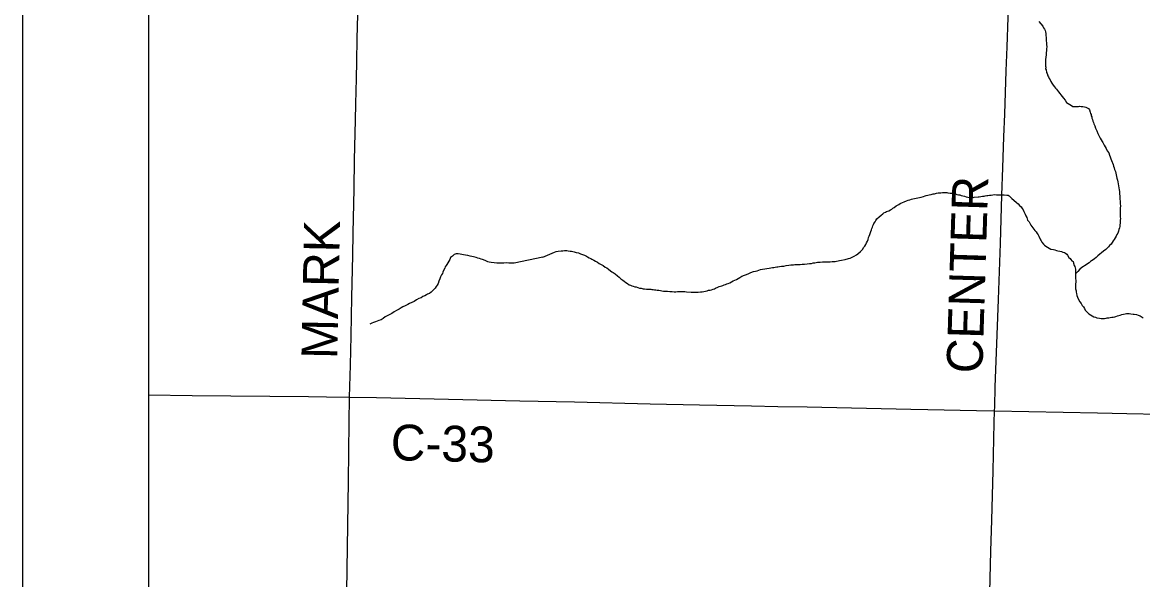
# Model space of a CAD drawing. Extents: x 2.1 to 73.9, y 4 to 26.
# Drawn here: x 41.859 to 42.746, y 22.261 to 22.702 of the extents above; entities that cross this region are included whole.
import ezdxf

# ---------------------------------------------------------------- set-up
doc = ezdxf.new("R2010")
doc.units = 0
for name, color, linetype in [('GM_X_County_Road', 7, 'Continuous'), ('GM_X_County_Road_Text', 7, 'Continuous'), ('GM_X_Minor_River', 7, 'Continuous'), ('GM_X_Township_Road', 7, 'Continuous'), ('GM_X_Township_Road_Text', 7, 'Continuous'), ('SH_Data', 7, 'Continuous')]:
    doc.layers.add(name, color=color, linetype=linetype)

msp = doc.modelspace()

# ---------------------------------------------------------------- linework, layer by layer
at = {"layer": 'GM_X_County_Road'}
for points in [[(42.11768, 22.40528), (42.11831, 22.43051), (42.11882, 22.45382), (42.11946, 22.48459), (42.12015, 22.51753), (42.12049, 22.53524), (42.12117, 22.57036), (42.12166, 22.59335), (42.12239, 22.62474), (42.12266, 22.63779), (42.12313, 22.65767), (42.12339, 22.67135), (42.12371, 22.68907), (42.12411, 22.70833), (42.12441, 22.72822), (42.12463, 22.73723), (42.12492, 22.74998), (42.12514, 22.76365), (42.12565, 22.78757), (42.12612, 22.80528), (42.12662, 22.82827), (42.1272, 22.85469), (42.12765, 22.87831), (42.12836, 22.90514)], [(41.95853, 22.40709), (41.99302, 22.40672), (42.08503, 22.40572), (42.09933, 22.40557), (42.11768, 22.40528)], [(42.11267, 21.90506), (42.11274, 21.91552), (42.11287, 21.92921), (42.11306, 21.99168), (42.11314, 22.01188), (42.11339, 22.03675), (42.11342, 22.04701), (42.11352, 22.06939), (42.11355, 22.08244), (42.11375, 22.10636), (42.11409, 22.1449), (42.11475, 22.19121), (42.11514, 22.22634), (42.1155, 22.2512), (42.11674, 22.33884), (42.11734, 22.38514), (42.11768, 22.40528)], [(42.11768, 22.40528), (42.13911, 22.40494), (42.19598, 22.40361), (42.25255, 22.40241), (42.29574, 22.40145), (42.35573, 22.40007), (42.39489, 22.39932), (42.43591, 22.39845), (42.45674, 22.39798), (42.48005, 22.39755), (42.56209, 22.39575), (42.57577, 22.39544), (42.61431, 22.39477), (42.62854, 22.39452)], [(42.62854, 22.39452), (42.71003, 22.39274), (42.73334, 22.39224), (42.75945, 22.39171), (42.78835, 22.39125), (42.81415, 22.3908), (42.87568, 22.38954), (42.90055, 22.38899), (42.93443, 22.38826), (42.96519, 22.38759), (42.99814, 22.38692), (43.02704, 22.3862), (43.08701, 22.38489), (43.12151, 22.38421), (43.12923, 22.38405)]]:
    msp.add_lwpolyline(points, dxfattribs=at)
at = {"layer": 'GM_X_Minor_River'}
for points in [[(42.66365, 22.70298), (42.66664, 22.69932), (42.66738, 22.69798), (42.66812, 22.69683), (42.66848, 22.69568), (42.66885, 22.69473), (42.66902, 22.69339), (42.66918, 22.69149), (42.66935, 22.69054), (42.66934, 22.6894), (42.66931, 22.68769), (42.66966, 22.68597), (42.66964, 22.68445), (42.66981, 22.68312), (42.66958, 22.68103), (42.66956, 22.6797), (42.66935, 22.67838), (42.66932, 22.67648), (42.6691, 22.67458), (42.66889, 22.67287), (42.66886, 22.67135), (42.66884, 22.66983), (42.66882, 22.6687), (42.6688, 22.66755), (42.66898, 22.6666), (42.66896, 22.66546), (42.66933, 22.66451), (42.66968, 22.6626), (42.67004, 22.66164), (42.67078, 22.65992), (42.67133, 22.65896), (42.67188, 22.65782), (42.67244, 22.65667), (42.67318, 22.65532), (42.67392, 22.65417), (42.67503, 22.65245), (42.67596, 22.6511), (42.67671, 22.65014), (42.67764, 22.64917), (42.67839, 22.64821), (42.67914, 22.64725), (42.68007, 22.64591), (42.681, 22.64475), (42.68212, 22.6434), (42.68305, 22.64206), (42.68435, 22.64052), (42.68547, 22.63879), (42.68942, 22.63626), (42.69037, 22.63567), (42.69132, 22.63566), (42.69283, 22.63544), (42.69398, 22.63561), (42.69493, 22.6356), (42.69588, 22.63577), (42.69721, 22.63556), (42.69835, 22.63554), (42.69968, 22.63533), (42.70081, 22.63494), (42.70176, 22.63454), (42.70289, 22.63395), (42.70382, 22.6328)], [(42.70382, 22.6328), (42.70418, 22.63108), (42.70454, 22.63013), (42.70491, 22.62917), (42.70508, 22.62822), (42.70545, 22.62726), (42.70562, 22.62631), (42.70599, 22.62535), (42.70635, 22.62402), (42.7069, 22.62287), (42.70726, 22.62172), (42.70781, 22.6202), (42.70854, 22.61847), (42.70946, 22.61618), (42.71038, 22.61407), (42.7113, 22.61216), (42.71203, 22.61044), (42.71296, 22.60909), (42.7137, 22.60794), (42.71426, 22.60698), (42.71482, 22.60602), (42.71537, 22.60487), (42.71611, 22.60372), (42.71685, 22.60238), (42.71777, 22.60047), (42.71889, 22.59874), (42.71943, 22.59702), (42.72017, 22.59568), (42.72072, 22.59415), (42.72107, 22.59281), (42.72235, 22.58956), (42.72272, 22.58842), (42.72327, 22.58708), (42.72362, 22.58555), (42.72417, 22.58402), (42.72453, 22.58269), (42.72489, 22.58135), (42.72506, 22.58021), (42.72542, 22.57868), (42.72577, 22.57716), (42.72613, 22.57582), (42.72649, 22.5743), (42.72666, 22.57277), (42.72701, 22.57125), (42.72718, 22.56954), (42.72735, 22.5682), (42.72751, 22.5663), (42.72767, 22.56459), (42.72783, 22.5625), (42.72798, 22.5604), (42.72795, 22.5585), (42.72812, 22.55679), (42.72809, 22.55508), (42.72807, 22.55356), (42.72804, 22.55204), (42.72802, 22.55071), (42.728, 22.54919), (42.72798, 22.54786), (42.72815, 22.54672), (42.72794, 22.54558), (42.72792, 22.54425), (42.7279, 22.54311), (42.72769, 22.54179), (42.72767, 22.54046), (42.72746, 22.53932), (42.72706, 22.538), (42.72666, 22.53667), (42.72607, 22.53516), (42.72529, 22.53422), (42.7247, 22.5329), (42.72392, 22.5314), (42.72333, 22.53027), (42.72255, 22.52914), (42.72177, 22.52782), (42.7208, 22.52651), (42.71964, 22.52538), (42.71867, 22.52445), (42.7179, 22.52351), (42.71674, 22.52239), (42.71481, 22.5209), (42.71038, 22.51717), (42.70903, 22.51605), (42.70768, 22.51493), (42.70653, 22.514), (42.70537, 22.51326), (42.70441, 22.5127), (42.70345, 22.51177), (42.70211, 22.51103), (42.70114, 22.5101), (42.6998, 22.50936), (42.69884, 22.5088), (42.69769, 22.50806), (42.69595, 22.50657), (42.6944, 22.50488), (42.69324, 22.50357), (42.69285, 22.5032), (42.69286, 22.50339)], [(42.54799, 22.55508), (42.54895, 22.55564), (42.55067, 22.55675), (42.55163, 22.55731), (42.5526, 22.55805), (42.55375, 22.5586), (42.55873, 22.5608), (42.56007, 22.56135), (42.5614, 22.56171), (42.56274, 22.56207), (42.56389, 22.56243), (42.56503, 22.56279), (42.56637, 22.56296), (42.5677, 22.56313), (42.56904, 22.56349), (42.57037, 22.56385), (42.57228, 22.56439), (42.57343, 22.56475), (42.57439, 22.56493), (42.57572, 22.56528), (42.57668, 22.56546), (42.5782, 22.56582), (42.57992, 22.56636), (42.58087, 22.56634), (42.58259, 22.56689), (42.58374, 22.56706), (42.58583, 22.56721), (42.58717, 22.56738), (42.58831, 22.56737), (42.58964, 22.56734), (42.59059, 22.56733), (42.59154, 22.56712), (42.59324, 22.56691), (42.59496, 22.56688), (42.5959, 22.56668), (42.59761, 22.56627), (42.59874, 22.56587), (42.59988, 22.56566), (42.60102, 22.56545), (42.60215, 22.56506), (42.60329, 22.56485), (42.60462, 22.56445), (42.60594, 22.56405), (42.60727, 22.56364), (42.60878, 22.56343), (42.6105, 22.56359), (42.61145, 22.56358), (42.6124, 22.56375), (42.61545, 22.56389), (42.6164, 22.56407), (42.61774, 22.56424), (42.61888, 22.56441), (42.62021, 22.56458), (42.62117, 22.56476), (42.62231, 22.56493), (42.62326, 22.5651), (42.62441, 22.56527), (42.62574, 22.56544), (42.62708, 22.56561), (42.62841, 22.56578), (42.62993, 22.56557), (42.63202, 22.56553), (42.63393, 22.56569), (42.63602, 22.56566), (42.6383, 22.56543), (42.63925, 22.56542), (42.64019, 22.56483), (42.64093, 22.56387), (42.64225, 22.56271), (42.64375, 22.56136), (42.64581, 22.55961), (42.64712, 22.55845), (42.64824, 22.55711), (42.64956, 22.55595), (42.65049, 22.55479), (42.65123, 22.55364), (42.65179, 22.55249), (42.65234, 22.55134), (42.6527, 22.5502), (42.65325, 22.54886), (42.65399, 22.54752), (42.65472, 22.54541), (42.65584, 22.54407), (42.65658, 22.54272), (42.65732, 22.54157), (42.65806, 22.54042), (42.65881, 22.53946), (42.65955, 22.5385), (42.66049, 22.53734), (42.66142, 22.53619), (42.66216, 22.53503), (42.66291, 22.53388), (42.66346, 22.53273), (42.66494, 22.53005), (42.6653, 22.52909), (42.66586, 22.52814), (42.66716, 22.52641), (42.6681, 22.52563), (42.66904, 22.52486), (42.67036, 22.52407), (42.67168, 22.52329)], [(42.41141, 22.49321), (42.41237, 22.49358), (42.41332, 22.49375), (42.41447, 22.49431), (42.41543, 22.49467), (42.41658, 22.49503), (42.41753, 22.4954), (42.41887, 22.49595), (42.42022, 22.49668), (42.42137, 22.49743), (42.4229, 22.49797), (42.42405, 22.49852), (42.42539, 22.49926), (42.42674, 22.5), (42.42827, 22.50112), (42.43038, 22.50184), (42.43191, 22.50258), (42.43382, 22.50331), (42.43555, 22.50404), (42.43746, 22.50477), (42.43918, 22.50512), (42.44051, 22.50548), (42.44185, 22.50584), (42.44319, 22.50639), (42.44472, 22.50675), (42.45006, 22.50761), (42.45139, 22.50778), (42.45253, 22.50795), (42.45368, 22.50812), (42.45482, 22.5083), (42.45597, 22.50847), (42.45692, 22.50864), (42.45825, 22.50881), (42.45978, 22.50898), (42.46149, 22.50914), (42.4634, 22.50968), (42.46569, 22.50984), (42.46702, 22.51), (42.46816, 22.50999), (42.46931, 22.51016), (42.47026, 22.51033), (42.47197, 22.5105), (42.47311, 22.51048), (42.47464, 22.51045), (42.47616, 22.51062), (42.47787, 22.51078), (42.48016, 22.51094), (42.48187, 22.5111), (42.4834, 22.51127), (42.48473, 22.51162), (42.48626, 22.51179), (42.48816, 22.51214), (42.49026, 22.5123), (42.49216, 22.51246), (42.49444, 22.51242), (42.49635, 22.51258), (42.49825, 22.51255), (42.49997, 22.51271), (42.50225, 22.51287), (42.50568, 22.51357), (42.5074, 22.51373), (42.51026, 22.51426), (42.51294, 22.51517), (42.51408, 22.51553), (42.51523, 22.51589), (42.51619, 22.51645), (42.51734, 22.517), (42.51907, 22.51811), (42.52022, 22.51885), (42.52234, 22.52072), (42.52389, 22.52221), (42.52506, 22.5241), (42.52583, 22.52503), (42.52661, 22.52635), (42.52702, 22.52767), (42.52779, 22.5288), (42.52839, 22.53031), (42.52879, 22.53183), (42.52919, 22.53296), (42.52959, 22.53409), (42.52998, 22.53504), (42.53039, 22.53655), (42.53098, 22.53787), (42.53138, 22.53901), (42.53177, 22.53995), (42.53217, 22.54108), (42.53257, 22.54203), (42.53296, 22.54297), (42.53393, 22.54429), (42.53452, 22.54523), (42.5353, 22.54654), (42.53703, 22.54804), (42.53858, 22.54934), (42.53993, 22.55065), (42.54089, 22.55121), (42.54204, 22.55195), (42.543, 22.55231), (42.54472, 22.55286), (42.54606, 22.55378), (42.54702, 22.55434), (42.54799, 22.55508)], [(42.27063, 22.51627), (42.24811, 22.51139), (42.24659, 22.51143), (42.24545, 22.51147), (42.24374, 22.51152), (42.24184, 22.51158), (42.23994, 22.51145), (42.23671, 22.51155), (42.23442, 22.51143), (42.23215, 22.5117), (42.22988, 22.51196), (42.22817, 22.5122), (42.22724, 22.51261), (42.22554, 22.51323), (42.22386, 22.51404), (42.22292, 22.51445), (42.22179, 22.51468), (42.22047, 22.5151), (42.21933, 22.51533), (42.21783, 22.51594), (42.21576, 22.51658), (42.2133, 22.51703), (42.21122, 22.51748), (42.20952, 22.51772), (42.20801, 22.51815), (42.20669, 22.51838), (42.20537, 22.51861), (42.20366, 22.51886), (42.20195, 22.51872), (42.2006, 22.51838), (42.19923, 22.51691), (42.19767, 22.51582), (42.19705, 22.51431), (42.19465, 22.5104), (42.19405, 22.50947), (42.19345, 22.50854), (42.19304, 22.50741), (42.19203, 22.50554), (42.19161, 22.50442), (42.19119, 22.50329), (42.19059, 22.50217), (42.18978, 22.50049), (42.18916, 22.49899), (42.18835, 22.4973), (42.18772, 22.49542), (42.18691, 22.49412), (42.18612, 22.493), (42.18532, 22.4917), (42.18413, 22.49022), (42.18315, 22.4893), (42.18217, 22.48838), (42.181, 22.48746), (42.17946, 22.48694), (42.1785, 22.4864), (42.17714, 22.48569), (42.17579, 22.48497), (42.17424, 22.48407), (42.17251, 22.48336), (42.17076, 22.48228), (42.16883, 22.4812), (42.1669, 22.48031), (42.16516, 22.47941), (42.1638, 22.4787), (42.16168, 22.47762), (42.15994, 22.47673), (42.15859, 22.47601), (42.15703, 22.47492), (42.15491, 22.47385), (42.15298, 22.47296), (42.15104, 22.47169), (42.1491, 22.47061), (42.14755, 22.46971), (42.14581, 22.46881), (42.14426, 22.46772), (42.1427, 22.46663), (42.14078, 22.46593), (42.13962, 22.4654), (42.13808, 22.46487), (42.13673, 22.46435), (42.1352, 22.46383), (42.13366, 22.4632)], [(42.27063, 22.51627), (42.28004, 22.52018), (42.28138, 22.52073), (42.2829, 22.5209), (42.28519, 22.52124), (42.28652, 22.52122), (42.28786, 22.52139), (42.28976, 22.52136), (42.2907, 22.52116), (42.29241, 22.52094), (42.29336, 22.52092), (42.2945, 22.52072), (42.29564, 22.52032), (42.29715, 22.51991), (42.29886, 22.51951), (42.30056, 22.51891), (42.30207, 22.51832), (42.30377, 22.51772), (42.30528, 22.51693), (42.30623, 22.51654), (42.30736, 22.51576), (42.30868, 22.51517), (42.30962, 22.51459), (42.31113, 22.5138), (42.31245, 22.51302), (42.31396, 22.51224), (42.31546, 22.51126), (42.31697, 22.51048), (42.31848, 22.50951), (42.32017, 22.50834), (42.3213, 22.50775), (42.32262, 22.50678), (42.32431, 22.50542), (42.32525, 22.50465), (42.32638, 22.50406), (42.32807, 22.50289), (42.32995, 22.50134), (42.33108, 22.50038), (42.33258, 22.49902), (42.33408, 22.49805), (42.33521, 22.49708), (42.33653, 22.49611), (42.33766, 22.49533), (42.33897, 22.49436), (42.34011, 22.49396), (42.34124, 22.49356), (42.34238, 22.49317), (42.34351, 22.49277), (42.34465, 22.49256), (42.34597, 22.49216), (42.3473, 22.49176), (42.34863, 22.49155), (42.35014, 22.49114), (42.35128, 22.49112), (42.3528, 22.49091), (42.35432, 22.49089), (42.35527, 22.49087), (42.35622, 22.49086), (42.35717, 22.49065), (42.35812, 22.49064), (42.35907, 22.49043), (42.36021, 22.49022), (42.36135, 22.49002), (42.36249, 22.49), (42.36381, 22.48979), (42.36495, 22.48958), (42.36628, 22.48937), (42.3678, 22.48934), (42.36951, 22.48913), (42.37122, 22.48891), (42.37312, 22.48888), (42.37464, 22.48886), (42.37597, 22.48883), (42.3773, 22.489), (42.37864, 22.48898), (42.37978, 22.48896), (42.3813, 22.48894), (42.3832, 22.48891), (42.38453, 22.4887), (42.38814, 22.48845), (42.38947, 22.48843), (42.39099, 22.48841), (42.39251, 22.48857), (42.39366, 22.48855), (42.39556, 22.48871), (42.39689, 22.48869), (42.39823, 22.48905), (42.39956, 22.48922), (42.4009, 22.48958), (42.40204, 22.48994), (42.40319, 22.49011), (42.40433, 22.49029), (42.40567, 22.49084), (42.40663, 22.4912), (42.40758, 22.49156), (42.40931, 22.49249), (42.41046, 22.49285), (42.41141, 22.49321)], [(42.67168, 22.52329), (42.67319, 22.52251), (42.67509, 22.52229), (42.67622, 22.52189), (42.67755, 22.52149), (42.67868, 22.52128), (42.6802, 22.52088), (42.68153, 22.52067), (42.68266, 22.52027), (42.6838, 22.51987), (42.68474, 22.51929), (42.68568, 22.5187), (42.68624, 22.51774), (42.68735, 22.51602), (42.68829, 22.51524), (42.68903, 22.51428), (42.68978, 22.51332), (42.69072, 22.51273), (42.69108, 22.5114), (42.69162, 22.50968), (42.69218, 22.50872), (42.69253, 22.50681), (42.69252, 22.50586), (42.69269, 22.50453), (42.69266, 22.5032), (42.69265, 22.50225), (42.69263, 22.50111), (42.69261, 22.49997), (42.6926, 22.49902), (42.69277, 22.49788), (42.69275, 22.49655), (42.69272, 22.49484), (42.69271, 22.49389), (42.69269, 22.49275), (42.69266, 22.49104), (42.69302, 22.48951), (42.6932, 22.48856), (42.69337, 22.48742), (42.69373, 22.48589), (42.69427, 22.48455), (42.695, 22.48264), (42.69593, 22.48073), (42.69705, 22.47938), (42.69798, 22.47803), (42.69891, 22.47688), (42.69984, 22.47553), (42.7002, 22.4742), (42.70114, 22.47342), (42.70207, 22.47227), (42.7032, 22.4713), (42.70715, 22.46896), (42.70848, 22.46856), (42.70961, 22.46816), (42.71151, 22.46775), (42.71303, 22.46773), (42.71436, 22.46771), (42.71569, 22.46768), (42.71683, 22.46786), (42.71779, 22.46803), (42.71893, 22.4682), (42.72008, 22.46837), (42.72141, 22.46854), (42.72255, 22.46872), (42.7237, 22.46889), (42.72465, 22.46925), (42.72599, 22.46961), (42.7279, 22.47034), (42.72924, 22.47089), (42.73058, 22.47106), (42.73191, 22.47142), (42.73306, 22.47159), (42.7342, 22.47157), (42.73515, 22.47156), (42.73648, 22.47134), (42.73819, 22.47113), (42.73914, 22.47092), (42.74084, 22.47071), (42.74236, 22.4703), (42.74387, 22.46971), (42.74538, 22.46873), (42.74632, 22.46815)]]:
    msp.add_lwpolyline(points, dxfattribs=at)
at = {"layer": 'GM_X_Township_Road'}
for points in [[(42.62854, 22.39452), (42.62862, 22.39758), (42.62908, 22.41342), (42.63003, 22.44075), (42.63157, 22.48268), (42.63308, 22.5271), (42.6342, 22.5653), (42.63502, 22.58705), (42.6359, 22.61158), (42.63658, 22.6296), (42.63777, 22.66376), (42.63847, 22.68271), (42.63921, 22.706), (42.63965, 22.71905), (42.64059, 22.74638), (42.64175, 22.77713), (42.64261, 22.79855), (42.64371, 22.83086), (42.64447, 22.85322), (42.6453, 22.87932), (42.64548, 22.89328)], [(42.6144, 21.89578), (42.6155, 21.91218), (42.61686, 21.95516), (42.61925, 22.03531), (42.62038, 22.07352), (42.62139, 22.10925), (42.62288, 22.16704), (42.62341, 22.18848), (42.62433, 22.22918), (42.62567, 22.28324), (42.62627, 22.30779), (42.62734, 22.34693), (42.62831, 22.38484), (42.62854, 22.39452)]]:
    msp.add_lwpolyline(points, dxfattribs=at)
at = {"layer": 'SH_Data'}
for p, q in [((41.85853, 25.00511), (41.85853, 18.00511)), ((41.95853, 24.90511), (41.95853, 18.10511))]:
    msp.add_line(p, q, dxfattribs=at)

# ---------------------------------------------------------------- texts
at = {"layer": 'GM_X_County_Road_Text'}
for s, rotation, p in [('MARK', 88.85411, (42.10789, 22.43533)), ('C-33', 358.62866, (42.15003, 22.35541))]:
    msp.add_text(s, height=0.028409, rotation=rotation, dxfattribs=at).set_placement(p)
at = {"layer": 'GM_X_Township_Road_Text'}
msp.add_text('CENTER', height=0.028409, rotation=88.23784, dxfattribs=at).set_placement((42.61879, 22.4238))

doc.saveas('drawing.dxf')
